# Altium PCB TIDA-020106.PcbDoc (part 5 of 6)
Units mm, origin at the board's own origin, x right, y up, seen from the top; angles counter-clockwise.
Board outline 158.53 x 83.25 mm, 6 copper layers (Top Layer, GND, Power, Sig4, GND (Mid4), Bottom Layer), stack 1.59 mm thick; 410 components, 255 nets, 1280 pads, 2405 vias.
Unrouted connection lines stored in the file: 294.
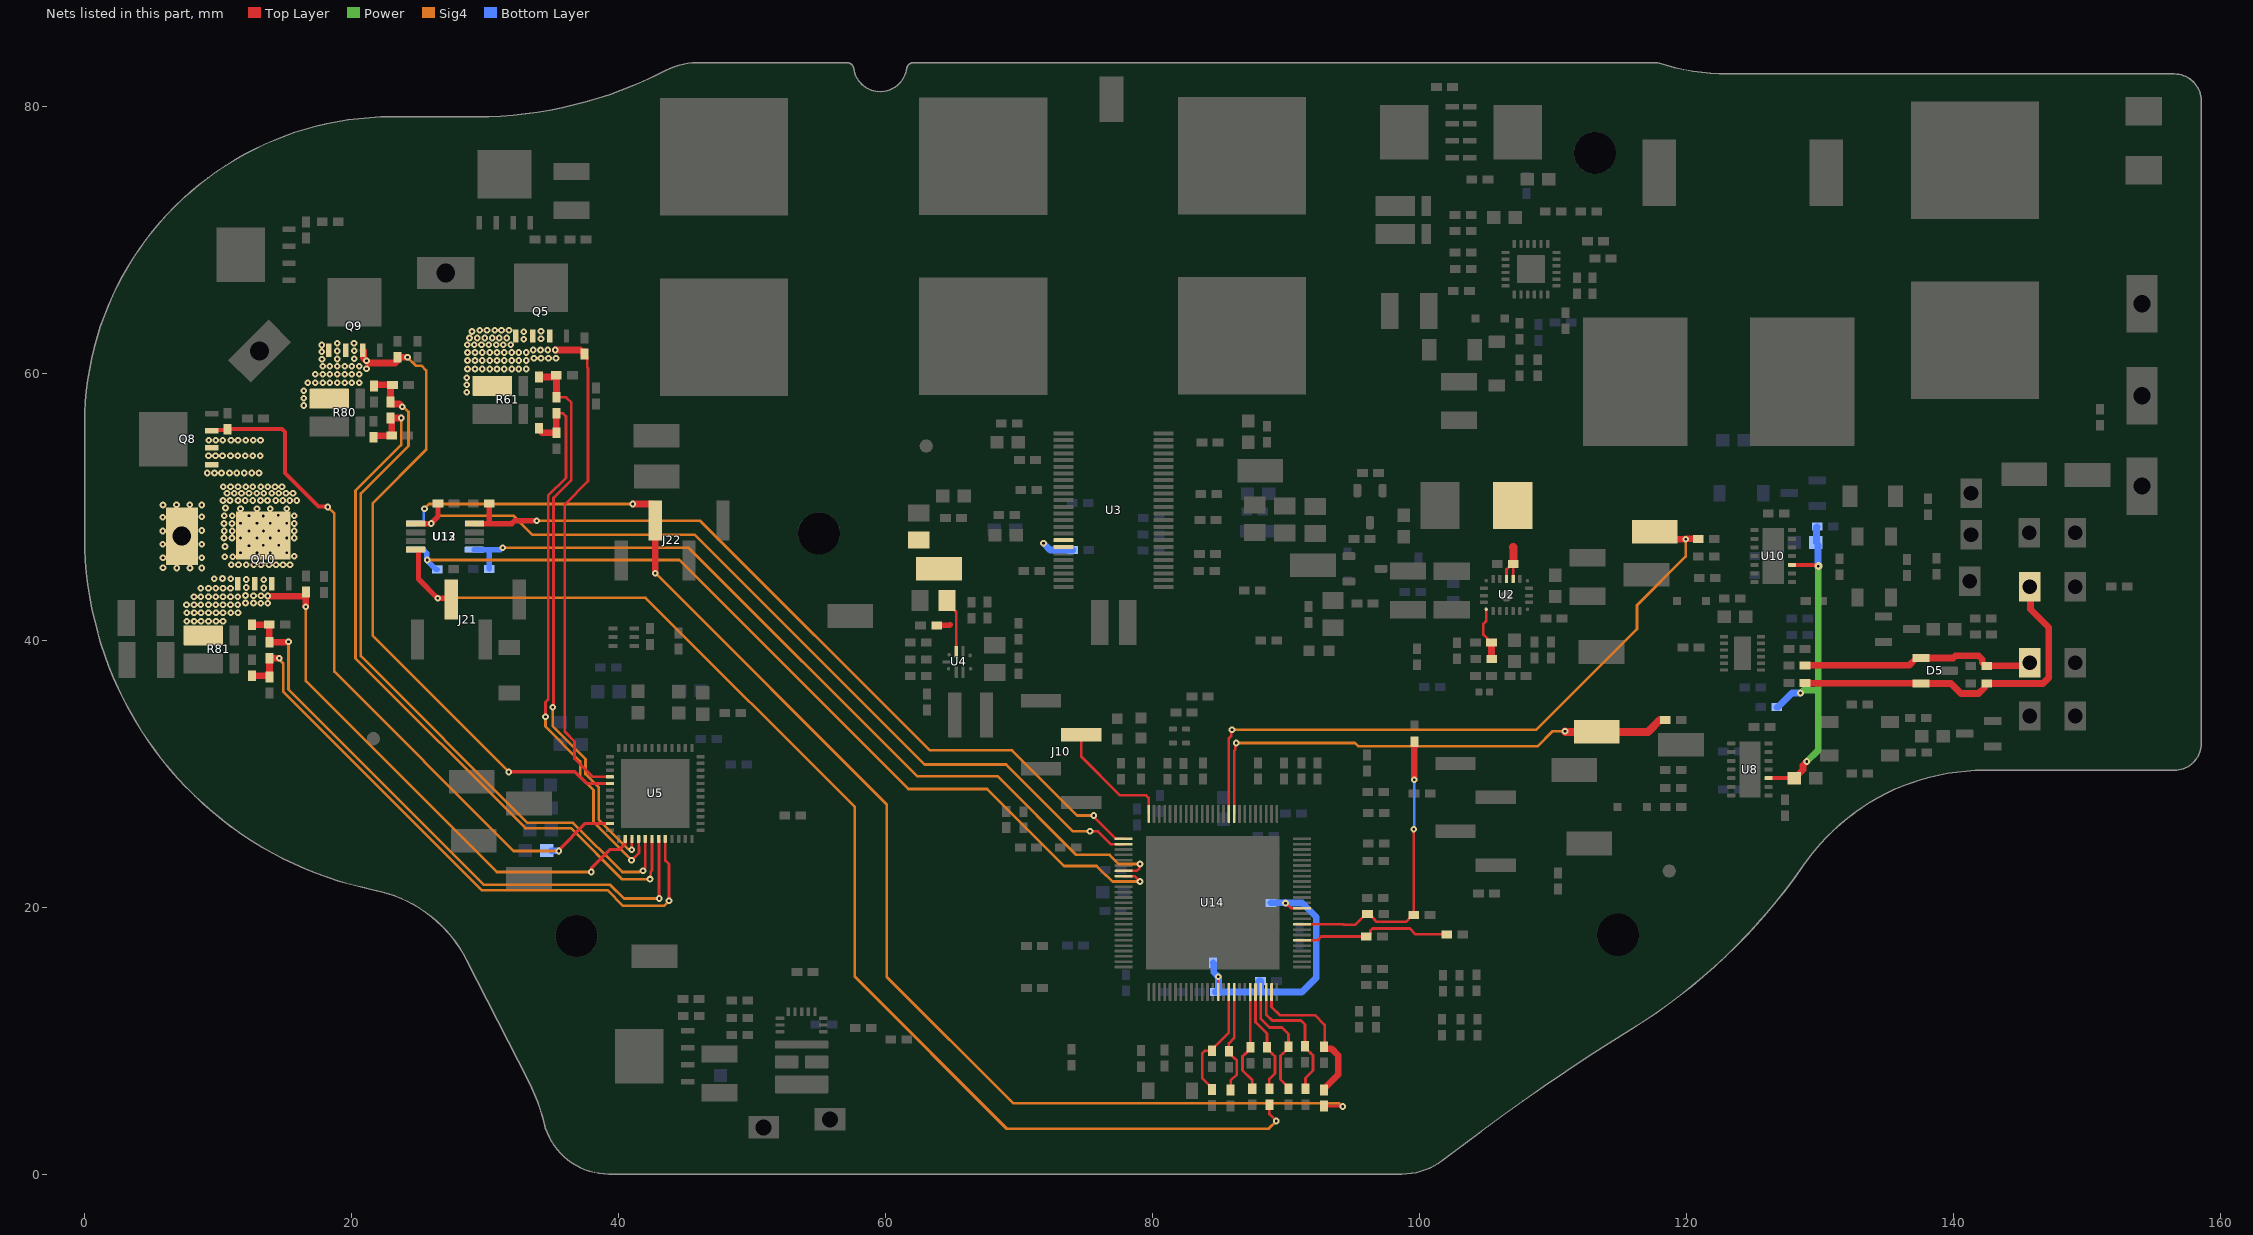
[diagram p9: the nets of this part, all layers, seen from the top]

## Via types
v1: diameter 0.5, hole 0.2, Top Layer to Bottom Layer, 2315 vias
v2: diameter 0.5, hole 0.2, Top Layer to Bottom Layer, tented both sides, 87 vias
v3: diameter 0.6, hole 0.2, Top Layer to Bottom Layer, 3 vias

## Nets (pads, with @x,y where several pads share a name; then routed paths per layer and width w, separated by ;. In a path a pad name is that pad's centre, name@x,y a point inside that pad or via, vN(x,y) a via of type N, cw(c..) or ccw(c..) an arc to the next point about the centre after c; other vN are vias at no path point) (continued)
SHC: C77.1 J9.1 Q8.1 Q8.2 Q8.3 Q10.5 R70.1 U5.47 | length 53.1
  Top Layer w0.25: v1(35.504,24.2) 35.504,24.258 37.51,26.265 U5.47@39.343,26.265
  Top Layer w0.3: Q8.3@9.511,55.682 9.566,55.737 10.637,55.737 R70.1@10.7,55.8 14.785,55.8 14.991,55.595 14.991,52.526 17.503,50.013 18.159,50.013 v1(18.197,49.975)
  Sig4 w0.2: v1(18.197,49.975) 18.697,49.476 18.697,37.642 32.138,24.2 v1(35.504,24.2)
  Bottom Layer w0.5: C77.1@34.972,24.225 35.479,24.225 v1(35.504,24.2)
  other v1: 6.888,45.406 7.888,45.406 8.765,45.406 5.871,45.422 10.986,45.656 11.527,45.656 12.095,45.656 12.671,45.656 13.202,45.656 13.806,45.656 14.329,45.653 14.858,45.656 15.385,45.656 5.871,46.179 8.765,46.179 10.492,46.253 11.091,46.253 15.695,46.291 11.673,46.542 12.91,46.542 13.894,46.542 15.131,46.542 10.515,47.009 12.313,47.061 13.381,47.095 14.547,47.095 5.855,47.179 8.765,47.179 10.442,47.645 11.042,47.645 11.673,47.647 12.91,47.647 13.894,47.647 15.131,47.647 15.695,47.645 5.855,48.179 10.447,48.174 11.046,48.174 12.313,48.174 13.4,48.174 15.695,48.174 14.547,48.2 8.765,48.214 10.442,48.732 11.042,48.732 15.695,48.732 11.673,48.764 12.91,48.764 13.894,48.764 15.131,48.764 5.855,49.214 8.765,49.252 13.381,49.3 10.453,49.326 11.052,49.326 12.313,49.318 15.695,49.326 14.509,49.353 11.673,49.842 12.91,49.842 13.894,49.842 15.131,49.842 10.553,49.9 5.871,50.124 6.879,50.133 8.765,50.124 7.879,50.149 10.364,50.461 10.886,50.458 11.485,50.461 12.025,50.461 12.594,50.461 13.169,50.461 13.7,50.461 14.305,50.461 14.827,50.458 15.357,50.461 15.884,50.461 10.665,51.006 14.547,51.006 11.205,51.009 11.745,51.009 12.313,51.009 12.889,51.009 13.42,51.009 14.024,51.009 15.076,51.009 15.603,51.009 10.379,51.481 10.919,51.481 11.488,51.481 12.063,51.481 12.594,51.481 13.198,51.481 13.721,51.478 14.25,51.481 14.777,51.481 9.192,52.514 9.721,52.517 10.244,52.514 10.848,52.514 11.379,52.514 11.955,52.514 12.523,52.514 13.063,52.514 9.27,53.817 9.799,53.82 10.322,53.817 10.926,53.817 11.457,53.817 12.033,53.817 12.601,53.817 13.142,53.817 9.299,54.971 9.829,54.973 10.352,54.971 10.956,54.971 11.487,54.971 12.062,54.971 12.631,54.971 13.171,54.971
SIN_P1: J21.3 R119.1 U12.8 | length 93.9
  Top Layer w0.2: R119.1@88.74,5.2 88.74,4.504 v1(89.261,3.984)
  Top Layer w0.4: U12.8@24.8,46.775 24.975,46.775 25,46.75 25,44.577 v1(26.439,43.138) 27.375,43.138 J21.3@27.47,43.043
  Sig4 w0.2: v1(26.439,43.138) 26.469,43.169 42.02,43.169 57.685,27.504 57.685,14.783 69.068,3.4 88.677,3.4 v1(89.261,3.984)
SIN_P2: J22.3 R123.1 U13.8 | length 101.1
  Top Layer w0.2: R123.1@92.847,5.102 94.202,5.102 v1(94.237,5.067)
  Top Layer w0.5: v1(41.054,50.191) 42.482,50.191 42.732,49.941 J22.3@42.732,48.963 42.743,48.952 v1(42.743,45.019)
  Sig4 w0.2: v1(25.451,49.848) 25.794,50.191 v1(41.054,50.191) ; v1(42.743,45.019) 60.079,27.682 60.079,14.777 69.559,5.297 93.97,5.297 94.2,5.067 v1(94.237,5.067)
  Bottom Layer w0.2: U13.8@24.789,48.727 25.283,48.727 25.408,48.852 25.408,49.805 v1(25.451,49.848)
SLA: Q5.1 Q5.2 Q5.3 R56.1 R61.2 U5.40 | length 37.2
  Top Layer w0.2: R56.1@37.441,61.427 37.641,61.227 37.641,60.437 37.699,60.379 37.699,51.902 35.961,50.165 35.961,33.137 36.694,32.404 36.694,31.116 38.045,29.765 U5.40@39.343,29.765
  Top Layer w0.5: v1(35.256,61.735) 37.133,61.735 37.291,61.577 37.391,61.577 37.441,61.527 R56.1@37.441,61.427 37.441,61.346 R56.1@37.391,61.296
  other v1: 28.631,58.562 28.631,59.119 28.631,59.662 28.678,60.304 29.235,60.304 29.778,60.304 30.348,60.304 30.883,60.304 31.435,60.304 32,60.304 32.521,60.304 33.078,60.304 28.678,60.942 29.235,60.942 29.778,60.942 30.348,60.942 30.883,60.942 31.435,60.942 32,60.942 32.521,60.942 33.078,60.942 33.653,61.113 34.187,61.113 34.739,61.113 35.304,61.113 28.678,61.541 29.235,61.541 29.778,61.541 30.348,61.541 30.883,61.541 31.435,61.541 32,61.541 32.521,61.541 33.078,61.541 33.604,61.735 34.138,61.735 34.691,61.735 28.663,62.136 29.184,62.136 29.718,62.136 30.271,62.136 30.835,62.136 31.356,62.136 31.913,62.136 32.88,62.527 34.187,62.572 28.82,62.627 29.412,62.627 29.965,62.627 30.529,62.627 31.05,62.627 31.607,62.627 32.88,63.088 29.018,63.115 34.187,63.132 29.589,63.203 30.141,63.203 30.706,63.203 31.226,63.203 31.784,63.203
SLB: Q9.1 Q9.2 Q9.3 R74.1 R80.2 U5.41 | length 49.9
  Top Layer w0.25: v1(31.76,30.127) 31.768,30.135 36.724,30.135 37.594,29.265 U5.41@39.343,29.265
  Top Layer w0.5: Q9.3@20.839,61.713 20.884,61.668 20.884,61.138 21.259,60.763 23.266,60.763 R74.1@23.516,61.013 ; R74.1@23.433,61.18 v1(24.182,61.18)
  Sig4 w0.2: v1(24.182,61.18) 24.8,60.562 25.216,60.562 25.584,60.194 25.584,54.259 21.588,50.263 21.588,40.315 31.76,30.142 v1(31.76,30.127)
  other v1: 16.403,57.569 16.403,58.112 16.403,58.683 16.719,59.287 17.262,59.287 17.833,59.287 18.367,59.287 18.92,59.287 19.484,59.287 20.005,59.287 20.562,59.287 17.262,59.925 17.833,59.925 18.367,59.925 18.92,59.925 19.484,59.925 20.005,59.925 20.562,59.925 21.108,60.321 17.833,60.524 18.367,60.524 18.92,60.524 19.484,60.524 20.005,60.524 20.562,60.524 21.105,60.923 17.776,61.039 18.927,61.056 20.204,61.081 17.761,61.594 18.927,61.651 20.204,61.668 17.761,62.11 18.927,62.23 20.177,62.23
SLC: Q10.1 Q10.2 Q10.3 R75.1 R81.2 U5.2 | length 40.7
  Top Layer w0.25: v1(37.943,22.626) 37.99,22.674 37.99,22.962 39.343,24.315 40.048,24.315 40.493,24.76 U5.2@40.493,25.115
  Top Layer w0.5: v1(13.708,43.303) 13.735,43.276 16.334,43.276 16.566,43.508 R75.1@16.566,43.608 ; v1(16.56,42.489) 16.566,42.495 R75.1@16.566,43.276
  Sig4 w0.2: v1(16.56,42.489) 16.571,42.477 16.571,36.927 30.872,22.626 v1(37.943,22.626)
  other v1: 7.638,41.42 8.196,41.42 8.716,41.42 9.281,41.42 9.833,41.42 10.368,41.42 7.638,42.058 8.196,42.058 8.716,42.058 9.281,42.058 9.833,42.058 10.368,42.058 10.938,42.058 11.481,42.058 7.627,42.654 8.185,42.654 8.705,42.654 9.27,42.654 9.822,42.654 10.357,42.654 10.927,42.654 11.47,42.654 12.048,42.777 12.646,42.777 13.19,42.769 13.708,42.769 8.185,43.253 8.705,43.253 9.27,43.253 9.822,43.253 10.357,43.253 10.927,43.253 11.47,43.253 12.646,43.314 13.202,43.312 12.048,43.343 8.705,43.891 9.27,43.891 9.822,43.891 10.357,43.891 10.927,43.891 13.407,43.901 12.095,43.935 13.415,44.526 12.095,44.535 9.715,44.6 10.936,44.6 10.322,44.61
SNA: C66.2 C71.1 R63.1 U5.4 | length 42.1
  Top Layer w0.2: v1(34.513,34.263) 34.513,35.345 34.714,35.546 34.714,50.824 36.05,52.16 36.05,56.762 35.827,56.984 C66.2@35.342,56.984 ; v1(40.959,23.522) 40.988,23.522 41.523,24.058 41.523,24.513 41.493,24.544 U5.4@41.493,25.115
  Top Layer w0.5: R63.1@34.049,55.817 34.049,55.765 34.289,55.525 C71.1@35.327,55.525 35.335,55.532 35.335,56.977 C66.2@35.342,56.984
  Sig4 w0.2: v1(34.513,34.263) 34.513,33.526 37.117,30.923 37.117,29.764 38.116,28.765 38.116,26.365 v1(40.959,23.522)
SNB: C81.2 C85.1 R82.1 U5.6 | length 55
  Top Layer w0.2: v1(42.34,22.1) 42.393,22.152 42.393,22.65 42.493,22.75 U5.6@42.493,25.115
  Top Layer w0.5: R82.1@21.629,55.198 21.629,55.26 21.679,55.31 C85.1@22.996,55.31 22.996,56.454 22.912,56.538 C81.2@22.912,56.638 v1(23.701,56.638)
  Sig4 w0.2: v1(23.701,56.638) 23.701,54.614 20.288,51.2 20.288,38.64 33.013,25.914 36.414,25.914 40.229,22.1 v1(42.34,22.1)
SNC: C82.2 C87.1 R83.1 U5.8 | length 46.5
  Top Layer w0.2: U5.8@43.493,25.115 43.493,23.494 43.773,23.214 v1(43.773,20.475)
  Top Layer w0.5: R83.1@12.534,37.337 13.797,37.337 C87.1@13.847,37.287 ; C87.1@13.847,37.242 C87.1@13.847,37.287 ; v1(14.577,38.633) C82.2@13.847,38.633 C87.1@13.847,37.287
  Sig4 w0.2: v1(14.577,38.633) 14.577,38.552 14.863,38.266 14.863,36.141 29.731,21.273 39.15,21.273 40.33,20.093 43.377,20.093 43.76,20.475 v1(43.773,20.475)
SOA_DRV3263: C78.1 R71.1 U14.17 | length 8
  Top Layer w0.2: R71.1@85.843,6.302 85.843,7.002 86.302,7.461 86.302,8.519 86.126,8.695 86.102,8.695 85.702,9.095 C78.1@85.702,9.195 85.702,9.797 86.102,10.197 U14.17@86.102,13.642
SOB_DRV3263: C79.1 R76.1 U14.23 | length 10.2
  Top Layer w0.2: U14.23@88.502,13.642 88.502,11.962 88.956,11.509 91.109,11.509 91.41,11.207 C79.1@91.41,9.571 91.41,9.471 91.81,9.071 91.834,9.071 92.01,8.895 92.01,7.771 91.445,7.206 R76.1@91.445,6.391
SOC_DRV3263: C80.1 R77.1 U14.22 | length 9.2
  Top Layer w0.2: U14.22@88.102,13.642 88.102,11.635 88.748,10.989 89.678,10.989 90.175,10.493 C80.1@90.175,9.552 90.175,9.452 89.775,9.052 89.751,9.052 89.575,8.876 89.575,7.091 90.175,6.491 R77.1@90.175,6.391
SPA: C66.1 C70.1 R60.1 U5.3 | length 42
  Top Layer w0.2: v1(35.063,34.961) 35.114,35.012 35.114,50.658 36.45,51.995 36.45,57.787 36.052,58.184 C66.1@35.342,58.184 35.342,58.223 C66.1@35.142,58.423 ; C70.1@35.193,59.697 C70.1@35.342,59.549 ; C66.1@35.342,58.284 35.342,58.689 ; v1(40.973,24.285) 40.983,24.295 40.983,25.105 U5.3@40.993,25.115
  Top Layer w0.5: R60.1@34.049,59.702 C70.1@35.098,59.702 ; C70.1@35.235,59.839 35.292,59.839 35.342,59.789 35.342,59.549 35.342,58.689
  Sig4 w0.2: v1(35.063,34.961) 35.063,33.542 37.517,31.088 37.517,29.958 38.516,28.958 38.516,26.533 40.706,24.343 40.916,24.343 v1(40.973,24.285)
SPB: C81.1 C84.1 R78.1 U5.5 | length 54.5
  Top Layer w0.2: v1(41.82,22.715) 41.82,22.797 41.993,22.97 U5.5@41.993,25.115
  Top Layer w0.5: R78.1@21.66,59.038 21.66,59.069 21.71,59.119 C84.1@22.912,59.119 ; C84.1@23.06,59.119 22.962,59.119 22.912,59.069 C81.1@22.912,57.838 22.912,57.738 22.962,57.688 23.578,57.688 v1(23.791,57.476)
  Sig4 w0.2: v1(23.791,57.476) 23.872,57.476 24.251,57.096 24.251,54.546 20.688,50.982 20.688,38.805 33.179,26.314 36.58,26.314 40.268,22.626 41.553,22.626 41.585,22.658 41.762,22.658 v1(41.82,22.715)
SPC: C82.1 C86.1 R79.1 U5.7 | length 46.4
  Top Layer w0.2: U5.7@42.993,25.115 43.017,25.091 43.017,20.667 v1(43.041,20.643)
  Top Layer w0.5: R79.1@12.522,41.157 C86.1@13.814,41.157 13.83,41.14 13.83,39.849 C82.1@13.847,39.833 15.216,39.833 v1(15.263,39.88)
  Sig4 w0.2: v1(15.263,39.88) 15.263,36.307 29.897,21.673 39.368,21.673 40.398,20.643 v1(43.041,20.643)
SW_U4: C20.2 L2.1 U2.13 U2.14 | length 3.8
  Top Layer w0.2: U2.14@106.502,44.581 106.502,45.298 106.915,45.711 C20.2@107.015,45.711 107.002,45.698 U2.13@107.002,44.581
  Top Layer w0.6: 107.002,46.969 107.015,46.956 C20.2@107.015,45.711
TMAG_COSP1: C111.1 R121.2 U14.20 | length 7.7
  Top Layer w0.2: C111.1@87.302,9.601 U14.20@87.302,13.642 ; C111.1@87.332,9.495 87.332,9.395 86.932,8.995 86.899,8.995 86.732,8.828 86.732,7.771 87.457,7.046 R121.2@87.457,6.4
TMAG_COSP2: C114.1 R125.2 U14.16 | length 8.7
  Top Layer w0.2: R125.2@84.456,6.345 84.456,6.445 83.703,7.199 83.703,9.027 83.925,9.249 C114.1@84.456,9.249 84.456,9.349 85.702,10.595 U14.16@85.702,13.642
TMAG_Q01: R120.2 U12.4 U14.76 | length 60.2
  Top Layer w0.2: 30.3,48.774 30.349,48.725 ; v1(75.594,26.858) 75.651,26.8 75.651,26.719 77.252,25.117 U14.76@77.827,25.117
  Top Layer w0.4: U12.4@29.2,48.725 30.349,48.725 31.979,48.725 32.195,48.941 v1(33.852,48.941) ; 30.3,48.774 R120.2@30.3,50.229
  Sig4 w0.2: v1(33.852,48.941) 46.104,48.941 63.305,31.741 69.459,31.741 74.342,26.858 v1(75.594,26.858)
TMAG_Q02: R124.2 U13.4 U14.82 | length 62.8
  Top Layer w0.2: U14.82@77.827,22.717 78.802,22.717 78.995,22.91 78.995,23.167 v1(79.052,23.224)
  Sig4 w0.2: v1(31.307,46.919) 45.246,46.919 62.367,29.798 68.395,29.798 74.275,23.919 76.76,23.919 77.455,23.224 v1(79.052,23.224)
  Bottom Layer w0.4: U13.4@29.189,46.777 30.36,46.777 ; R124.2@30.3,45.327 30.3,46.717 30.36,46.777 ; v1(31.307,46.919) 31.28,46.919 31.137,46.777 30.36,46.777
TMAG_Q11: R122.2 U12.5 U14.77 | length 65.2
  Top Layer w0.2: v1(75.308,25.671) 75.898,25.671 76.852,24.717 U14.77@77.827,24.717
  Top Layer w0.4: U12.5@24.8,48.725 24.803,48.728 25.961,48.728 v1(25.964,48.732) 25.964,48.759 26.471,49.265 R122.2@26.471,50.246
  Sig4 w0.2: v1(25.964,48.732) 26.554,49.323 32.102,49.323 33.523,47.902 45.696,47.902 62.917,30.682 69.02,30.682 74.03,25.671 v1(75.308,25.671)
TMAG_Q12: R126.2 U13.5 U14.83 | length 67.3
  Top Layer w0.2: U14.83@77.827,22.317 78.64,22.317 79.04,21.917 v1(79.052,21.917)
  Sig4 w0.2: v1(25.65,45.995) 44.54,45.995 61.693,28.842 67.596,28.842 73.356,23.082 75.801,23.082 76.508,22.374 76.54,22.374 76.996,21.917 v1(79.052,21.917)
  Bottom Layer w0.4: U13.5@24.789,46.777 24.814,46.752 25.388,46.752 25.623,46.518 25.623,46.049 25.65,46.022 v1(25.65,45.995) 25.669,45.976 25.669,45.939 26.315,45.293 R126.2@26.415,45.293
TMAG_SINP1: C110.1 R119.2 U14.21 | length 8
  Top Layer w0.2: U14.21@87.702,13.642 87.702,11.387 88.565,10.524 C110.1@88.565,9.495 88.565,9.395 88.965,8.995 88.989,8.995 89.165,8.819 89.165,7.546 88.74,7.122 R119.2@88.74,6.4
TMAG_SINP2: C113.1 R123.2 U14.24 | length 11.7
  Top Layer w0.2: U14.24@88.902,13.642 88.902,12.522 89.516,11.909 92.152,11.909 92.883,11.178 92.883,9.588 C113.1@92.847,9.552
  Top Layer w0.5: R123.2@92.847,6.302 92.847,6.402 93.894,7.449 93.894,8.89 93.382,9.402 92.897,9.402 92.847,9.452 C113.1@92.847,9.552
TX_CAN1: R101.1 TP17.1 U14.59 | length 38.5
  Top Layer w0.2: U14.59@86.102,26.992 86.102,30.38 86.097,30.385 86.097,31.706 86.19,31.799 86.19,32.237 v1(86.247,32.294)
  Top Layer w0.6: v1(110.888,33.162) 110.921,33.129 TP17.1@113.269,33.129 115.269,33.129 117.102,33.129 118.002,34.029 R101.1@118.393,34.029
  Sig4 w0.2: v1(86.247,32.294) 95.147,32.294 95.4,32.041 108.807,32.041 109.928,33.162 v1(110.888,33.162)
TX_CAN2: R111.1 TP18.1 U14.60 | length 51.6
  Top Layer w0.2: U14.60@85.702,26.992 85.702,30.214 85.697,30.219 85.697,32.638 85.881,32.822 85.881,33.23 v1(85.939,33.288)
  Top Layer w0.5: TP18.1@117.594,47.563 TP18.1@117.622,47.591 ; TP18.1@117.606,48.112 118.155,47.563 v1(119.918,47.563) 119.946,47.591 R111.1@120.854,47.591
  Sig4 w0.2: v1@85.953,33.288 108.74,33.288 116.277,40.824 116.277,42.613 119.918,46.254 v1(119.918,47.563)
UART_RX: J10.2 U14.75 | length 9.2
  Top Layer w0.2: J10.2@74.649,32.915 74.649,31.267 77.544,28.372 79.511,28.372 79.702,28.18 U14.75@79.702,26.992
VCC_6V0: C40.1 C41.1 C42.1 C56.1 TP4.1 U3.41 U3.42 U4.6 | length 7.7
  Top Layer w0.2: C56.1@64.593,42.967 64.593,42.802 65.286,42.109 U4.6@65.286,39.128
  Top Layer w0.4: C41.1@63.813,41.111 64.786,41.111 64.832,41.157
  Top Layer w0.5: C40.1@62.324,47.497 C40.1@62.49,47.497
  Bottom Layer w0.5: v1(71.815,47.255) 72.319,46.751 C42.1@74.021,46.751
VDDA_3V3: C133.1 C135.1 C136.1 L10.1 U14.14 U14.37 | length 22.3
  Top Layer w0.2: U14.14@84.902,13.642 v1(84.902,14.79) ; v1(89.952,20.302) 89.96,20.302 90.345,19.917 U14.37@91.177,19.917
  Bottom Layer w0.5: C135.1@84.525,15.83 84.575,15.78 84.575,15.118 v1(84.902,14.79) ; C133.1@84.702,13.642 C133.1@84.802,13.642 ; v1@84.924,14.77 84.924,13.864 84.852,13.792 84.852,13.692 C133.1@84.802,13.642 ; L10.1@87.927,14.415 87.977,14.465 L10.1@88.077,14.465 88.077,13.667 88.102,13.642 ; C136.1@88.864,20.317 89.937,20.317 v1(89.952,20.302) 91.202,20.302 92.26,19.244 92.26,14.731 91.172,13.642 88.102,13.642 ; C133.1@84.802,13.642 88.102,13.642
VMON: C118.2 R130.2 R131.2 U14.34 | length 22.1
  Top Layer w0.2: U14.34@91.177,18.717 94.3,18.717 94.332,18.686 95.178,18.686 95.888,19.396 R131.2@95.988,19.396 ; R131.2@96.095,19.501 96.195,19.501 96.595,19.101 96.595,19.076 96.771,18.901 98.971,18.901 99.466,19.396 C118.2@99.566,19.396 99.544,19.417 v1(99.544,25.83)
  Top Layer w0.5: v1(99.603,29.532) R130.2@99.603,32.387
  Bottom Layer w0.2: v1(99.544,25.83) 99.603,25.889 v1(99.603,29.532)
VSNS: R32.2 R34.2 U2.1 | length 4.1
  Top Layer w0.2: U2.1@104.983,42.312 104.983,41.441 104.767,41.224 104.767,40.417 105.077,40.107 105.077,40.007 105.277,39.807 R34.2@105.377,39.807
  Top Layer w0.5: R34.2@105.377,39.807 105.382,39.802 105.382,38.577 R32.2@105.387,38.572
VSUP: C102.1 C106.1 R97.1 R99.1 U8.10 U10.10 | length 27
  Top Layer w0.3: U8.10@126.136,29.658 C102.1@127.898,29.658 ; U10.10@127.884,45.64 129.678,45.64 129.777,45.54 v3(129.859,45.54)
  Top Layer w0.5: C102.1@127.898,29.658 128.078,29.658 128.709,30.289 128.709,30.624 v1(128.99,30.905)
  Power w0.5: v1(128.524,36.037) 128.731,36.244 129.859,36.244 ; v1(128.99,30.905) 129.859,31.773 129.859,36.244 ; v3(129.859,45.54) 129.859,36.244
  Bottom Layer w0.5: R97.1@126.736,34.982 126.836,34.982 127.891,36.037 v1(128.524,36.037) ; C106.1@129.703,47.35 129.721,47.368 129.721,48.451 129.771,48.501 R99.1@129.783,48.501 ; C106.1@129.839,47.126 129.839,45.559 v3(129.859,45.54)
WSN: C94.2 D5.1 J2.1 R88.2 | length 18.1
  Top Layer w0.5: R88.2@128.859,38.105 136.654,38.105 137.154,38.605 137.504,38.605 D5.1@137.554,38.655 139.957,38.655 140.128,38.826 141.869,38.826 142.133,38.562 142.133,38.326 142.383,38.076 C94.2@142.483,38.076 145.476,38.076 J2.1@145.7,38.3 J2.1@145.374,38.626
WSP: C90.2 D5.2 J1.1 R86.2 | length 26.2
  Top Layer w0.5: R86.2@128.859,36.787 128.875,36.771 137.539,36.771 D5.2@137.554,36.755 139.801,36.755 140.549,36.007 141.869,36.007 C90.2@142.332,36.471 ; C90.2@142.482,36.757 142.49,36.75 146.686,36.75 147.13,37.194 147.13,40.929 145.75,42.309 J1.1@145.75,44
WSSO: C88.2 R84.2 U14.31 | length 11.6
  Top Layer w0.2: U14.31@91.177,17.517 92.338,17.517 92.647,17.826 92.673,17.8 96.098,17.8 96.298,18 96.298,18.234 96.463,18.4 99.256,18.4 99.693,17.963 R84.2@102.027,17.963
pads on no net: D11.2 FID1.1 FID2.1 FID3.1 LBL1.0 MP1. MP2. MP3. MP4. U1.3 U1.8 U1.17 U1.21 U1.25 U2.10 U2.12 U2.16 U2.18 U3.21 U3.22 U3.23 U3.24 U3.25 U3.26 U3.27 U3.28 U3.30 U3.31 U3.43 U4.1 U8. U10. U12.3 U12.6 U13.3 U13.6 U14.9 U14.12 U14.30 Y1.1
copper on no net:
  other v2: 108.336,66.989 107.536,67.789 108.336,67.789 109.136,67.789 108.336,68.589

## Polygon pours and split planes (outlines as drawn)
48V/12V_P on Top Layer "Top Layer-48V/12V_P" (solid, remove dead copper, pour order 224): 78 vertices, not listed, extent -0.3,0 121.664,83.4
48V/12V_P on Top Layer "TOP_LAYER_48V/12V_P_P015" (solid, pour order 15): 101.078,45.711 101.178,45.811 104.45,45.811 105.164,45.098 105.164,44.364 105.106,44.306 104.556,44.306 104.062,43.812 101.598,43.812 101.078,44.333
NetC7_2 on Top Layer "Top Layer-NetC7_2" (solid, remove dead copper, pour order 11): 101.936,82.362 101.936,73.958 102.091,73.803 104.741,73.803 105.041,74.102 105.041,82.509 104.837,82.713 102.287,82.713
GND on Top Layer "Top Layer-GND" (solid, remove dead copper, pour order 195): 72 vertices, not listed, extent 4.839,0.07 158.678,73.445
SLC on Top Layer "TOP_LAYER_SLC_P186" (solid, pour order 186): 19 vertices, not listed, extent 7.336,39.576 14.414,44.941
SLA on Top Layer "TOP_LAYER_SLA_P190" (solid, pour order 190): 28.348,62.783 29.018,63.453 35.188,63.453 35.549,63.092 35.549,60.729 35.242,60.421 33.628,60.421 33.352,60.145 33.352,58.291 33.281,58.22 28.629,58.22 28.348,58.502
SLB on Top Layer "TOP_LAYER_SLB_P189" (solid, pour order 189): 16.08,57.487 16.08,59.577 17.364,60.861 17.364,62.187 17.705,62.527 21.198,62.527 21.501,62.225 21.501,60.002 20.928,59.43 20.928,57.386 20.808,57.266 16.303,57.266
VCC_6V0 on Top Layer "Top Layer-VCC_6V0" (solid, pour order 185): 32 vertices, not listed, extent 61.697,39.603 74.068,48.165
GND on Top Layer "TOP_LAYER_GND_P180" (solid, pour order 180): 35.084,72.604 35.084,71.171 35.439,70.817 37.816,70.817 38.025,71.026 38.025,72.347 37.768,72.604 36.895,72.604
GND on Top Layer "TOP_LAYER_GND_P021" (solid, pour order 21): 74.385,55.858 74.385,43.621 74.755,43.251 79.359,43.251 79.777,43.669 79.777,55.816 79.49,56.103 74.63,56.103
GND on Top Layer "TOP_LAYER_GND_P009" (solid, remove dead copper, pour order 9): 17 vertices, not listed, extent 99.361,58.309 111.4,66.039
OUTB_EPB on Top Layer "TOP_LAYER_OUTB_EPB_P045" (solid, pour order 45): 17 vertices, not listed, extent 48.587,1.314 53.465,8.971
OUTA_EPB on Top Layer "TOP_LAYER_OUTA_EPB_P046" (solid, pour order 46): 53.955,8.776 53.955,7.945 55.77,7.945 56.239,7.476 56.239,5.834 56.048,5.644 54.228,5.644 53.535,4.951 53.535,2.052 54.535,1.051 58.182,1.051 59.226,2.095 59.226,5.946 56.327,8.845 54.023,8.845
48V/12V_BDC on Top Layer "TOP_LAYER_48V/12V_BDC_P043" (solid, pour order 43): 18 vertices, not listed, extent 44.633,6.594 55.841,10.076
SHC on Top Layer "TOP_LAYER_SHC_P034" (solid, pour order 34): 19 vertices, not listed, extent 4.311,44.438 16.193,56.144
SHB on Top Layer "TOP_LAYER_SHB_P033" (solid, pour order 33): 17 vertices, not listed, extent 8.735,57.787 22.844,70.011
SHA on Top Layer "TOP_LAYER_SHA_P030" (solid, pour order 30): 33.007,72.204 24.786,72.204 24.168,71.586 24.168,65.051 25.063,64.155 36.399,64.155 36.807,64.562 36.807,67.253 33.362,70.698 33.362,71.849
NetC38_1 on Top Layer "TOP_LAYER_NETC38_1_P025" (solid, pour order 25): 81.49,43.022 81.802,43.334 81.802,45.505 81.949,45.652 82.429,45.652 82.839,45.242 82.839,41.927 80.514,39.603 77.48,39.603 77.45,39.632 77.458,39.64 77.458,43.022
NetC39_1 on Top Layer "TOP_LAYER_NETC39_1_P024" (solid, pour order 24): 71.217,44.895 71.217,42.813 74.427,39.603 76.588,39.603 76.648,39.662 76.648,42.925 76.551,43.022 72.958,43.022 72.057,43.923 72.057,45.008 71.312,45.008
3.3V on Top Layer "TOP_LAYER_3.3V_P020" (solid, remove dead copper, pour order 20): 65.286,52.241 65.492,52.448 67.89,52.448 68.884,51.454 68.884,49.247 68.493,48.856 65.434,48.856 65.286,49.005
1.25V on Top Layer "TOP_LAYER_1.25V_P019" (solid, pour order 19): 66.201,32.935 66.891,32.244 68.435,32.244 68.884,32.693 68.884,36.117 69.399,36.632 70.496,36.632 70.873,37.008 70.873,37.648 70.571,37.95 69.178,37.95 68.884,38.244 66.405,38.244 66.201,38.04
NetL4_1 on Top Layer "TOP_LAYER_NETL4_1_P018" (solid, pour order 18): 64.211,36.399 64.677,36.865 65.496,36.865 65.6,36.969 65.6,38.02 65.71,38.129 65.918,38.129 65.971,38.076 65.971,32.429 65.786,32.244 64.584,32.244 64.211,32.617
12V on Top Layer "TOP_LAYER_12V_P016" (solid, remove dead copper, pour order 16): 22 vertices, not listed, extent 79.999,42.126 95.755,48.856
12V_Cobra on Top Layer "TOP_LAYER_12V_COBRA_P013" (solid, remove dead copper, pour order 13): 96.75,46.987 98.003,48.24 99.562,48.24 99.9,48.577 99.9,52.192 100.239,52.531 103.671,52.531 104.127,52.075 104.127,47.019 101.259,44.151 97.103,44.151 96.75,44.504
SW_U4 on Top Layer "TOP_LAYER_SW_U4_P012" (solid, remove dead copper, pour order 12): 105.621,45.596 105.621,46.392 105.002,47.011 105.002,52.088 105.509,52.594 108.177,52.594 109.086,51.686 109.086,46.864 107.629,45.407 105.81,45.407
NetQ2_5 on Top Layer "TOP_LAYER_NETQ2_5_P005" (solid, remove dead copper, pour order 5): 94.423,82.577 94.423,73.604 96.368,71.658 99.861,71.658 101.583,73.38 101.583,80.696 99.217,83.062 94.907,83.062
48V/12V_IN_FILTERED on Top Layer "TOP_LAYER_48V/12V_IN_FILTERED_P002" (solid, remove dead copper, pour order 2): 105.579,76.136 105.579,82.135 106.697,83.254 119.046,83.254 122,80.3 122,69.882 120.947,68.829 116.585,68.829 115.806,69.608 115.806,74.515 114.781,75.54 105.985,75.54 105.584,75.941
48V/12V_IN on Top Layer "TOP_LAYER_48V/12V_IN_P000" (solid, pour order 0): 126,74.68 126,80.3 128.11,82.41 147.39,82.41 152.953,76.847 156.853,76.847 157.6,76.1 157.6,63.266 156.334,62 150.455,62 149,63.455 149,68.55 147.668,69.882 127.791,69.882 126.015,71.658
GND on Bottom Layer "BOTTOM_LAYER_GND_P228" (solid, pour order 228): 34.889,72.026 34.889,70.953 37.215,68.628 37.215,66.046 38.858,66.046 40.31,67.498 41.32,67.498 41.32,67.787 38.299,70.809 38.299,71.809 37.768,72.339 35.066,72.339 34.93,72.204
NetC7_2 on Bottom Layer "Top Layer-NetC7_2" (solid, remove dead copper, pour order 221): 101.936,82.362 101.936,73.958 102.091,73.803 104.741,73.803 105.041,74.102 105.041,82.509 104.837,82.713 102.287,82.713
SLA on Bottom Layer "BOTTOM_LAYER_SLA_P216" (solid, pour order 216): 28.348,62.783 29.018,63.453 35.188,63.453 35.549,63.092 35.549,60.729 35.242,60.421 33.628,60.421 33.352,60.145 33.352,58.291 33.281,58.22 28.629,58.22 28.348,58.502
SLB on Bottom Layer "BOTTOM_LAYER_SLB_P215" (solid, pour order 215): 16.08,57.487 16.08,59.577 17.364,60.861 17.364,62.187 17.705,62.527 21.198,62.527 21.501,62.225 21.501,60.002 20.928,59.43 20.928,57.386 20.808,57.266 16.303,57.266
SLC on Bottom Layer "BOTTOM_LAYER_SLC_P214" (solid, pour order 214): 19 vertices, not listed, extent 7.336,39.576 14.414,44.941
GND on Bottom Layer "Bottom Layer-GND" (solid, remove dead copper, pour order 198): 72 vertices, not listed, extent 4.839,0.07 158.678,73.445
48V/12V_P on Bottom Layer "Bottom Layer-48V/12V_P" (solid, pour order 110): 52 vertices, not listed, extent -0.3,0 100.491,83.4
SHC on Bottom Layer "BOTTOM_LAYER_SHC_P109" (solid, pour order 109): 19 vertices, not listed, extent 4.311,44.438 16.193,56.144
SHB on Bottom Layer "BOTTOM_LAYER_SHB_P108" (solid, pour order 108): 17 vertices, not listed, extent 8.735,57.787 22.844,70.011
SHA on Bottom Layer "BOTTOM_LAYER_SHA_P107" (solid, pour order 107): 33.007,72.204 24.786,72.204 24.168,71.586 24.168,65.051 25.063,64.155 36.399,64.155 36.807,64.562 36.807,67.253 33.362,70.698 33.362,71.849
NetQ2_5 on Bottom Layer "BOTTOM_LAYER_NETQ2_5_P106" (solid, remove dead copper, pour order 106): 94.423,82.577 94.423,73.604 96.368,71.658 99.861,71.658 101.583,73.38 101.583,80.696 99.217,83.062 94.907,83.062
48V/12V_IN_FILTERED on Bottom Layer "BOTTOM_LAYER_48V/12V_IN_FILTERED_P105" (solid, remove dead copper, pour order 105): 105.579,76.136 105.579,82.135 106.697,83.254 119.046,83.254 122,80.3 122,69.882 120.947,68.829 116.585,68.829 115.806,69.608 115.806,74.515 114.781,75.54 105.985,75.54 105.584,75.941
48V/12V_IN on Bottom Layer "BOTTOM_LAYER_48V/12V_IN_P104" (solid, pour order 104): 126,74.68 126,80.3 128.11,82.41 147.39,82.41 152.953,76.847 156.853,76.847 157.6,76.1 157.6,63.266 156.334,62 150.455,62 149,63.455 149,68.55 147.668,69.882 127.791,69.882 126.015,71.658
48V/12V_BDC on Bottom Layer "BOTTOM_LAYER_48V/12V_BDC_P049" (solid, pour order 49): 19 vertices, not listed, extent 44.657,6.614 55.865,10.096
1.25V on Bottom Layer "BOTTOM_LAYER_1.25V_P041" (solid, pour order 41): 20 vertices, not listed, extent 75.368,14.563 79.286,27.499
12V on Bottom Layer "BOTTOM_LAYER_12V_P017" (solid, remove dead copper, pour order 17): 80.102,49.427 80.102,46.412 80.282,46.232 82.196,46.232 82.749,46.785 82.749,48.987 82.059,49.677 80.291,49.677 80.099,49.485
GND on Sig4 "SIG4_GND_P225" (solid, pour order 225): 34.889,72.026 34.889,70.953 37.215,68.628 37.215,66.046 38.858,66.046 40.31,67.498 41.32,67.498 41.32,67.787 38.299,70.809 38.299,71.809 37.768,72.339 35.066,72.339 34.93,72.204
NetC7_2 on Sig4 "Top Layer-NetC7_2" (solid, remove dead copper, pour order 219): 101.936,82.362 101.936,73.958 102.091,73.803 104.741,73.803 105.041,74.102 105.041,82.509 104.837,82.713 102.287,82.713
SLA on Sig4 "SIG4_SLA_P210" (solid, pour order 210): 28.348,62.783 29.018,63.453 35.188,63.453 35.549,63.092 35.549,60.729 35.242,60.421 33.628,60.421 33.352,60.145 33.352,58.291 33.281,58.22 28.629,58.22 28.348,58.502
SLB on Sig4 "SIG4_SLB_P209" (solid, pour order 209): 16.08,57.487 16.08,59.577 17.364,60.861 17.364,62.187 17.705,62.527 21.198,62.527 21.501,62.225 21.501,60.002 20.928,59.43 20.928,57.386 20.808,57.266 16.303,57.266
SLC on Sig4 "SIG4_SLC_P208" (solid, pour order 208): 19 vertices, not listed, extent 7.336,39.576 14.414,44.941
GND on Sig4 "Sig4-GND" (solid, remove dead copper, pour order 196): 72 vertices, not listed, extent 4.839,0.07 158.678,73.445
48V/12V_BDC on Sig4 "SIG4_48V/12V_BDC_P178" (solid, pour order 178): 19 vertices, not listed, extent 44.627,6.59 55.835,10.072
48V/12V_P on Sig4 "Sig4-48V/12V_P" (solid, pour order 96): 54 vertices, not listed, extent -0.3,0 100.491,83.4
OUTA_EPB on Sig4 "SIG4_OUTA_EPB_P118" (solid, pour order 118): 53.955,8.776 53.955,7.945 55.77,7.945 56.239,7.476 56.239,5.834 56.048,5.644 54.228,5.644 53.535,4.951 53.535,2.052 54.535,1.051 58.182,1.051 59.226,2.095 59.226,5.946 56.327,8.845 54.023,8.845
OUTB_EPB on Sig4 "SIG4_OUTB_EPB_P117" (solid, pour order 117): 17 vertices, not listed, extent 48.587,1.314 53.465,8.971
SHC on Sig4 "SIG4_SHC_P095" (solid, pour order 95): 19 vertices, not listed, extent 4.311,44.438 16.193,56.144
SHB on Sig4 "SIG4_SHB_P094" (solid, pour order 94): 17 vertices, not listed, extent 8.735,57.787 22.844,70.011
SHA on Sig4 "SIG4_SHA_P093" (solid, pour order 93): 33.007,72.204 24.786,72.204 24.168,71.586 24.168,65.051 25.063,64.155 36.399,64.155 36.807,64.562 36.807,67.253 33.362,70.698 33.362,71.849
NetQ2_5 on Sig4 "SIG4_NETQ2_5_P092" (solid, remove dead copper, pour order 92): 94.423,82.577 94.423,73.604 96.368,71.658 99.861,71.658 101.583,73.38 101.583,80.696 99.217,83.062 94.907,83.062
48V/12V_IN_FILTERED on Sig4 "SIG4_48V/12V_IN_FILTERED_P091" (solid, remove dead copper, pour order 91): 105.579,76.136 105.579,82.135 106.697,83.254 119.046,83.254 122,80.3 122,69.882 120.947,68.829 116.585,68.829 115.806,69.608 115.806,74.515 114.781,75.54 105.985,75.54 105.584,75.941
48V/12V_IN on Sig4 "SIG4_48V/12V_IN_P090" (solid, pour order 90): 126,74.68 126,80.3 128.11,82.41 147.39,82.41 152.953,76.847 156.853,76.847 157.6,76.1 157.6,63.266 156.334,62 150.455,62 149,63.455 149,68.55 147.668,69.882 127.791,69.882 126.015,71.658
1.25V on Sig4 "SIG4_1.25V_P042" (solid, pour order 42): 79.086,17.917 79.286,17.718 79.286,16.746 80.238,15.795 82.102,15.795 82.102,14.653 81.865,14.415 77.764,14.415 77.292,14.888 77.292,17.382 77.827,17.917
1.25V on Sig4 "SIG4_1.25V_P040" (solid, pour order 40): 21 vertices, not listed, extent 66.191,22.473 90.52,36.718
GND on GND "GND_GND_P226" (solid, pour order 226): 34.889,72.026 34.889,70.953 37.215,68.628 37.215,66.046 38.858,66.046 40.31,67.498 41.32,67.498 41.32,67.787 38.299,70.809 38.299,71.809 37.768,72.339 35.066,72.339 34.93,72.204
NetC7_2 on GND "Top Layer-NetC7_2" (solid, remove dead copper, pour order 218): 101.936,82.362 101.936,73.958 102.091,73.803 104.741,73.803 105.041,74.102 105.041,82.509 104.837,82.713 102.287,82.713
SLA on GND "GND_SLA_P204" (solid, pour order 204): 28.348,62.783 29.018,63.453 35.188,63.453 35.549,63.092 35.549,60.729 35.242,60.421 33.628,60.421 33.352,60.145 33.352,58.291 33.281,58.22 28.629,58.22 28.348,58.502
SLB on GND "GND_SLB_P203" (solid, pour order 203): 16.08,57.487 16.08,59.577 17.364,60.861 17.364,62.187 17.705,62.527 21.198,62.527 21.501,62.225 21.501,60.002 20.928,59.43 20.928,57.386 20.808,57.266 16.303,57.266
SLC on GND "GND_SLC_P202" (solid, pour order 202): 19 vertices, not listed, extent 7.336,39.576 14.414,44.941
GND on GND "GND-GND" (solid, remove dead copper, pour order 193): 72 vertices, not listed, extent 4.839,0.07 158.678,73.445
48V/12V_P on GND "GND-48V/12V_P" (solid, pour order 82): 53 vertices, not listed, extent -0.3,0 100.491,83.4
SHC on GND "GND_SHC_P081" (solid, pour order 81): 19 vertices, not listed, extent 4.311,44.438 16.193,56.144
SHB on GND "GND_SHB_P080" (solid, pour order 80): 18 vertices, not listed, extent 8.735,57.787 22.844,70.011
SHA on GND "GND_SHA_P079" (solid, pour order 79): 33.007,72.204 24.786,72.204 24.168,71.586 24.168,65.051 25.063,64.155 36.399,64.155 36.807,64.562 36.807,67.253 33.362,70.698 33.362,71.849
NetQ2_5 on GND "GND_NETQ2_5_P078" (solid, remove dead copper, pour order 78): 94.423,82.577 94.423,73.604 96.368,71.658 99.861,71.658 101.583,73.38 101.583,80.696 99.217,83.062 94.907,83.062
48V/12V_IN_FILTERED on GND "GND_48V/12V_IN_FILTERED_P077" (solid, remove dead copper, pour order 77): 105.579,76.136 105.579,82.135 106.697,83.254 119.046,83.254 122,80.3 122,69.882 120.947,68.829 116.585,68.829 115.806,69.608 115.806,74.515 114.781,75.54 105.985,75.54 105.584,75.941
48V/12V_IN on GND "GND_48V/12V_IN_P076" (solid, pour order 76): 126,74.68 126,80.3 128.11,82.41 147.39,82.41 152.953,76.847 156.853,76.847 157.6,76.1 157.6,63.266 156.334,62 150.455,62 149,63.455 149,68.55 147.668,69.882 127.791,69.882 126.015,71.658
NetC7_2 on Power "Top Layer-NetC7_2" (solid, remove dead copper, pour order 217): 101.936,82.362 101.936,73.958 102.091,73.803 104.741,73.803 105.041,74.102 105.041,82.509 104.837,82.713 102.287,82.713
SLA on Power "POWER_SLA_P207" (solid, pour order 207): 28.348,62.783 29.018,63.453 35.188,63.453 35.549,63.092 35.549,60.729 35.242,60.421 33.628,60.421 33.352,60.145 33.352,58.291 33.281,58.22 28.629,58.22 28.348,58.502
SLB on Power "POWER_SLB_P206" (solid, pour order 206): 16.08,57.487 16.08,59.577 17.364,60.861 17.364,62.187 17.705,62.527 21.198,62.527 21.501,62.225 21.501,60.002 20.928,59.43 20.928,57.386 20.808,57.266 16.303,57.266
SLC on Power "POWER_SLC_P205" (solid, pour order 205): 19 vertices, not listed, extent 7.336,39.576 14.414,44.941
3.3V on Power "Power-3.3V" (solid, remove dead copper, pour order 194): 72 vertices, not listed, extent 4.839,0.07 158.678,73.445
OUTA_EPB on Power "POWER_OUTA_EPB_P175" (solid, pour order 175): 53.955,8.776 53.955,7.945 55.77,7.945 56.239,7.476 56.239,5.834 56.048,5.644 54.228,5.644 53.535,4.951 53.535,2.052 54.535,1.051 58.182,1.051 59.226,2.095 59.226,5.946 56.327,8.845 54.023,8.845
OUTB_EPB on Power "POWER_OUTB_EPB_P174" (solid, pour order 174): 17 vertices, not listed, extent 48.587,1.314 53.465,8.971
48V/12V_BDC on Power "POWER_48V/12V_BDC_P173" (solid, pour order 173): 19 vertices, not listed, extent 44.627,6.59 55.835,10.072
3.3V on Power "POWER_3.3V_P172" (solid, pour order 172): 18 vertices, not listed, extent 35.281,0 62.446,15.181
48V/12V_P on Power "Power-48V/12V_P" (solid, pour order 89): 53 vertices, not listed, extent -0.3,0 100.491,83.4
OUTA_EPB on Power "POWER_OUTA_EPB_P120" (solid, pour order 120): 53.955,8.776 53.955,7.945 55.77,7.945 56.239,7.476 56.239,5.834 56.048,5.644 54.228,5.644 53.535,4.951 53.535,2.052 54.535,1.051 58.182,1.051 59.226,2.095 59.226,5.946 56.327,8.845 54.023,8.845
OUTB_EPB on Power "POWER_OUTB_EPB_P119" (solid, pour order 119): 17 vertices, not listed, extent 48.587,1.314 53.465,8.971
SHC on Power "POWER_SHC_P088" (solid, pour order 88): 19 vertices, not listed, extent 4.311,44.438 16.193,56.144
SHB on Power "POWER_SHB_P087" (solid, pour order 87): 17 vertices, not listed, extent 8.735,57.787 22.844,70.011
SHA on Power "POWER_SHA_P086" (solid, pour order 86): 33.007,72.204 24.786,72.204 24.168,71.586 24.168,65.051 25.063,64.155 36.399,64.155 36.807,64.562 36.807,67.253 33.362,70.698 33.362,71.849
NetQ2_5 on Power "POWER_NETQ2_5_P085" (solid, remove dead copper, pour order 85): 94.423,82.577 94.423,73.604 96.368,71.658 99.861,71.658 101.583,73.38 101.583,80.696 99.217,83.062 94.907,83.062
48V/12V_IN_FILTERED on Power "POWER_48V/12V_IN_FILTERED_P084" (solid, remove dead copper, pour order 84): 105.579,76.136 105.579,82.135 106.697,83.254 119.046,83.254 122,80.3 122,69.882 120.947,68.829 116.585,68.829 115.806,69.608 115.806,74.515 114.781,75.54 105.985,75.54 105.584,75.941
48V/12V_IN on Power "POWER_48V/12V_IN_P083" (solid, pour order 83): 126,74.68 126,80.3 128.11,82.41 147.39,82.41 152.953,76.847 156.853,76.847 157.6,76.1 157.6,63.266 156.334,62 150.455,62 149,63.455 149,68.55 147.668,69.882 127.791,69.882 126.015,71.658
GND on GND (Mid4) "GND_GND_P227" (solid, pour order 227): 34.889,72.026 34.889,70.953 37.215,68.628 37.215,66.046 38.858,66.046 40.31,67.498 41.32,67.498 41.32,67.787 38.299,70.809 38.299,71.809 37.768,72.339 35.066,72.339 34.93,72.204
NetC7_2 on GND (Mid4) "Top Layer-NetC7_2" (solid, remove dead copper, pour order 220): 101.936,82.362 101.936,73.958 102.091,73.803 104.741,73.803 105.041,74.102 105.041,82.509 104.837,82.713 102.287,82.713
SLA on GND (Mid4) "GND_SLA_P213" (solid, pour order 213): 28.348,62.783 29.018,63.453 35.188,63.453 35.549,63.092 35.549,60.729 35.242,60.421 33.628,60.421 33.352,60.145 33.352,58.291 33.281,58.22 28.629,58.22 28.348,58.502
SLB on GND (Mid4) "GND_SLB_P212" (solid, pour order 212): 16.08,57.487 16.08,59.577 17.364,60.861 17.364,62.187 17.705,62.527 21.198,62.527 21.501,62.225 21.501,60.002 20.928,59.43 20.928,57.386 20.808,57.266 16.303,57.266
SLC on GND (Mid4) "GND_SLC_P211" (solid, pour order 211): 19 vertices, not listed, extent 7.336,39.576 14.414,44.941
GND on GND (Mid4) "GND-GND 1" (solid, remove dead copper, pour order 197): 72 vertices, not listed, extent 4.839,0.07 158.678,73.445
48V/12V_P on GND (Mid4) "GND-48V/12V_P 1" (solid, pour order 103): 52 vertices, not listed, extent -0.3,0 100.491,83.4
SHC on GND (Mid4) "GND_SHC_P102" (solid, pour order 102): 19 vertices, not listed, extent 4.311,44.438 16.193,56.144
SHB on GND (Mid4) "GND_SHB_P101" (solid, pour order 101): 17 vertices, not listed, extent 8.735,57.787 22.844,70.011
SHA on GND (Mid4) "GND_SHA_P100" (solid, pour order 100): 33.007,72.204 24.786,72.204 24.168,71.586 24.168,65.051 25.063,64.155 36.399,64.155 36.807,64.562 36.807,67.253 33.362,70.698 33.362,71.849
NetQ2_5 on GND (Mid4) "GND_NETQ2_5_P099" (solid, remove dead copper, pour order 99): 94.423,82.577 94.423,73.604 96.368,71.658 99.861,71.658 101.583,73.38 101.583,80.696 99.217,83.062 94.907,83.062
48V/12V_IN_FILTERED on GND (Mid4) "GND_48V/12V_IN_FILTERED_P098" (solid, remove dead copper, pour order 98): 105.579,76.136 105.579,82.135 106.697,83.254 119.046,83.254 122,80.3 122,69.882 120.947,68.829 116.585,68.829 115.806,69.608 115.806,74.515 114.781,75.54 105.985,75.54 105.584,75.941
48V/12V_IN on GND (Mid4) "GND_48V/12V_IN_P097" (solid, pour order 97): 126,74.68 126,80.3 128.11,82.41 147.39,82.41 152.953,76.847 156.853,76.847 157.6,76.1 157.6,63.266 156.334,62 150.455,62 149,63.455 149,68.55 147.668,69.882 127.791,69.882 126.015,71.658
